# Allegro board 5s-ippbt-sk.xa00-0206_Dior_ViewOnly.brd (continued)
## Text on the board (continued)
BOTTOM: list("[Physical] BOTTOM" "89.Pad/Pad Direct Connect" "NOT_ALLOWED [(PWR_20)]" "ALL_ALLOWED" "" "DRC ERROR CLASS/BOTTOM" "[ThruPin] GND (<uTiL>cId2142<uTiL>.29) (-71.0 1946.0)" "[SmdPin] GND (<uTiL>cId2142<uTiL>.25) (-35.0 1910.0)" list(-71.000000 1946.000000) nil)@@@list("amy_chou" "2015/01/12 09:58:12" nil "P143000034-PC" "5s-ippbt-sk.x01")@@@list("jennifer_hsu" "2015/01/12 14:37:07" nil "p143000039-pc" "5s-ippbt-sk.x01") | list("[Physical] BOTTOM" "91.Pad/Pad Direct Connect" "NOT_ALLOWED [(PWR_20)]" "ALL_ALLOWED" "" "DRC ERROR CLASS/BOTTOM" "[ThruPin] GND (<uTiL>cId2142<uTiL>.28) (-71.0 1874.0)" "[SmdPin] GND (<uTiL>cId2142<uTiL>.25) (-35.0 1910.0)" list(-71.000000 1874.000000) nil)@@@list("amy_chou" "2015/01/12 09:58:14" nil "P143000034-PC" "5s-ippbt-sk.x01")@@@list("jennifer_hsu" "2015/01/12 14:37:08" nil "p143000039-pc" "5s-ippbt-sk.x01") | list("[Physical] BOTTOM" "88.Pad/Pad Direct Connect" "NOT_ALLOWED [(PWR_20)]" "ALL_ALLOWED" "" "DRC ERROR CLASS/BOTTOM" "[ThruPin] GND (<uTiL>cId2142<uTiL>.27) (1.0 1946.0)" "[SmdPin] GND (<uTiL>cId2142<uTiL>.25) (-35.0 1910.0)" list(1.000000 1946.000000) nil)@@@list("amy_chou" "2015/01/12 09:58:12" nil "P143000034-PC" "5s-ippbt-sk.x01")@@@list("jennifer_hsu" "2015/01/12 14:37:07" nil "p143000039-pc" "5s-ippbt-sk.x01") | list("[Physical] BOTTOM" "90.Pad/Pad Direct Connect" "NOT_ALLOWED [(PWR_20)]" "ALL_ALLOWED" "" "DRC ERROR CLASS/BOTTOM" "[ThruPin] GND (<uTiL>cId2142<uTiL>.26) (1.0 1874.0)" "[SmdPin] GND (<uTiL>cId2142<uTiL>.25) (-35.0 1910.0)" list(1.000000 1874.000000) nil)@@@list("amy_chou" "2015/01/12 09:58:13" nil "P143000034-PC" "5s-ippbt-sk.x01")@@@list("jennifer_hsu" "2015/01/12 14:37:08" nil "p143000039-pc" "5s-ippbt-sk.x01") | list("[Physical] BOTTOM" "93.Pad/Pad Direct Connect" "NOT_ALLOWED [(PWR_20)]" "ALL_ALLOWED" "" "DRC ERROR CLASS/BOTTOM" "[ThruPin] GND (<uTiL>cId4668<uTiL>.23) (79.5 2715.5)" "[SmdPin] GND (<uTiL>cId4668<uTiL>.21) (100.0 2695.0)" list(79.500000 2715.500000) nil)@@@list("amy_chou" "2015/01/12 09:58:15" nil "P143000034-PC" "5s-ippbt-sk.x01")@@@list("jennifer_hsu" "2015/01/12 14:37:09" nil "p143000039-pc" "5s-ippbt-sk.x01") | list("[Physical] BOTTOM" "95.Pad/Pad Direct Connect" "NOT_ALLOWED [(PWR_20)]" "ALL_ALLOWED" "" "DRC ERROR CLASS/BOTTOM" "[ThruPin] GND (<uTiL>cId4668<uTiL>.25) (79.5 2674.5)" "[SmdPin] GND (<uTiL>cId4668<uTiL>.21) (100.0 2695.0)" list(79.500000 2674.500000) nil)@@@list("amy_chou" "2015/01/12 09:58:16" nil "P143000034-PC" "5s-ippbt-sk.x01")@@@list("jennifer_hsu" "2015/01/12 14:37:09" nil "p143000039-pc" "5s-ippbt-sk.x01") | list("[Physical] BOTTOM" "99.Pad/Pad Direct Connect" "NOT_ALLOWED [(PWR_20)]" "ALL_ALLOWED" "" "DRC ERROR CLASS/BOTTOM" "[ThruPin] GND (<uTiL>cId3539<uTiL>.22) (109.5 960.5)" "[SmdPin] GND (<uTiL>cId3539<uTiL>.21) (130.0 940.0)" list(109.500000 960.500000) nil)@@@list("amy_chou" "2015/01/12 09:58:18" nil "P143000034-PC" "5s-ippbt-sk.x01")@@@list("jennifer_hsu" "2015/01/12 14:37:11" nil "p143000039-pc" "5s-ippbt-sk.x01") | list("[Physical] BOTTOM" "98.Pad/Pad Direct Connect" "NOT_ALLOWED [(PWR_20)]" "ALL_ALLOWED" "" "DRC ERROR CLASS/BOTTOM" "[ThruPin] GND (<uTiL>cId3539<uTiL>.23) (109.5 919.5)" "[SmdPin] GND (<uTiL>cId3539<uTiL>.21) (130.0 940.0)" list(109.500000 919.500000) nil)@@@list("amy_chou" "2015/01/12 09:58:18" nil "P143000034-PC" "5s-ippbt-sk.x01")@@@list("jennifer_hsu" "2015/01/12 14:37:10" nil "p143000039-pc" "5s-ippbt-sk.x01") | list("[Physical] BOTTOM" "92.Pad/Pad Direct Connect" "NOT_ALLOWED [(PWR_20)]" "ALL_ALLOWED" "" "DRC ERROR CLASS/BOTTOM" "[ThruPin] GND (<uTiL>cId4668<uTiL>.22) (120.5 2715.5)" "[SmdPin] GND (<uTiL>cId4668<uTiL>.21) (100.0 2695.0)" list(120.500000 2715.500000) nil)@@@list("amy_chou" "2015/01/12 09:58:14" nil "P143000034-PC" "5s-ippbt-sk.x01")@@@list("jennifer_hsu" "2015/01/12 14:37:08" nil "p143000039-pc" "5s-ippbt-sk.x01") | list("[Physical] BOTTOM" "94.Pad/Pad Direct Connect" "NOT_ALLOWED [(PWR_20)]" "ALL_ALLOWED" "" "DRC ERROR CLASS/BOTTOM" "[ThruPin] GND (<uTiL>cId4668<uTiL>.24) (120.5 2674.5)" "[SmdPin] GND (<uTiL>cId4668<uTiL>.21) (100.0 2695.0)" list(120.500000 2674.500000) nil)@@@list("amy_chou" "2015/01/12 09:58:15" nil "P143000034-PC" "5s-ippbt-sk.x01")@@@list("jennifer_hsu" "2015/01/12 14:37:09" nil "p143000039-pc" "5s-ippbt-sk.x01") | list("[Physical] BOTTOM" "97.Pad/Pad Direct Connect" "NOT_ALLOWED [(PWR_20)]" "ALL_ALLOWED" "" "DRC ERROR CLASS/BOTTOM" "[ThruPin] GND (<uTiL>cId3539<uTiL>.24) (150.5 960.5)" "[SmdPin] GND (<uTiL>cId3539<uTiL>.21) (130.0 940.0)" list(150.500000 960.500000) nil)@@@list("amy_chou" "2015/01/12 09:58:17" nil "P143000034-PC" "5s-ippbt-sk.x01")@@@list("jennifer_hsu" "2015/01/12 14:37:10" nil "p143000039-pc" "5s-ippbt-sk.x01") | list("[Physical] BOTTOM" "96.Pad/Pad Direct Connect" "NOT_ALLOWED [(PWR_20)]" "ALL_ALLOWED" "" "DRC ERROR CLASS/BOTTOM" "[ThruPin] GND (<uTiL>cId3539<uTiL>.25) (150.5 919.5)" "[SmdPin] GND (<uTiL>cId3539<uTiL>.21) (130.0 940.0)" list(150.500000 919.500000) nil)@@@list("amy_chou" "2015/01/12 09:58:16" nil "P143000034-PC" "5s-ippbt-sk.x01")@@@list("jennifer_hsu" "2015/01/12 14:37:10" nil "p143000039-pc" "5s-ippbt-sk.x01") | list("[Physical] BOTTOM" "83.Pad/Pad Direct Connect" "NOT_ALLOWED [(PWR_20)]" "ALL_ALLOWED" "" "DRC ERROR CLASS/BOTTOM" "[SmdPin] +1P5V (<uTiL>cId4455<uTiL>.2) (930.5 490.0)" "[SmdPin] +1P5V (<uTiL>cId4514<uTiL>.1) (935.0 497.62)" list(935.000000 497.620000) nil)@@@list("amy_chou" "2015/01/12 09:58:09" nil "P143000034-PC" "5s-ippbt-sk.x01")@@@list("jennifer_hsu" "2015/01/12 14:37:05" nil "p143000039-pc" "5s-ippbt-sk.x01") | list("[Physical] BOTTOM" "67.Pad/Pad Direct Connect" "NOT_ALLOWED [100OHM(DP_4/10|9/2.5/200)]" "ALL_ALLOWED" "" "DRC ERROR CLASS/BOTTOM" "[SmdPin] LAN_MDI0_P_C (<uTiL>cId4647<uTiL>.2) (1273.27 3573.46)" "[SmdPin] LAN_MDI0_P_C (<uTiL>cId4415<uTiL>.1) (1274.25 3572.48)" list(1274.250000 3572.480000) nil)@@@list("amy_chou" "2015/01/12 09:58:00" nil "P143000034-PC" "5s-ippbt-sk.x01")@@@list("jennifer_hsu" "2015/01/12 14:36:59" nil "p143000039-pc" "5s-ippbt-sk.x01") | list("[Physical] BOTTOM" "68.Pad/Pad Direct Connect" "NOT_ALLOWED [100OHM(DP_4/10|9/2.5/200)]" "ALL_ALLOWED" "" "DRC ERROR CLASS/BOTTOM" "[SmdPin] LAN_MDI0_P (<uTiL>cId4647<uTiL>.1) (1273.27 3506.54)" "[SmdPin] LAN_MDI0_P (<uTiL>cId4415<uTiL>.2) (1274.25 3507.52)" list(1274.250000 3507.520000) nil)@@@list("amy_chou" "2015/01/12 09:58:00" nil "P143000034-PC" "5s-ippbt-sk.x01")@@@list("jennifer_hsu" "2015/01/12 14:36:59" nil "p143000039-pc" "5s-ippbt-sk.x01") | list("[Physical] BOTTOM" "69.Pad/Pad Direct Connect" "NOT_ALLOWED [100OHM(DP_4/10|9/2.5/200)]" "ALL_ALLOWED" "" "DRC ERROR CLASS/BOTTOM" "[SmdPin] LAN_MDI0_N_C (<uTiL>cId4647<uTiL>.3) (1306.73 3573.46)" "[SmdPin] LAN_MDI0_N_C (<uTiL>cId4415<uTiL>.3) (1305.75 3572.48)" list(1305.750000 3572.480000) nil)@@@list("amy_chou" "2015/01/12 09:58:01" nil "P143000034-PC" "5s-ippbt-sk.x01")@@@list("jennifer_hsu" "2015/01/12 14:36:59" nil "p143000039-pc" "5s-ippbt-sk.x01") | list("[Physical] BOTTOM" "70.Pad/Pad Direct Connect" "NOT_ALLOWED [100OHM(DP_4/10|9/2.5/200)]" "ALL_ALLOWED" "" "DRC ERROR CLASS/BOTTOM" "[SmdPin] LAN_MDI0_N (<uTiL>cId4647<uTiL>.4) (1306.73 3506.54)" "[SmdPin] LAN_MDI0_N (<uTiL>cId4415<uTiL>.4) (1305.75 3507.52)" list(1305.750000 3507.520000) nil)@@@list("amy_chou" "2015/01/12 09:58:01" nil "P143000034-PC" "5s-ippbt-sk.x01")@@@list("jennifer_hsu" "2015/01/12 14:37:00" nil "p143000039-pc" "5s-ippbt-sk.x01") | list("[Physical] BOTTOM" "63.Pad/Pad Direct Connect" "NOT_ALLOWED [100OHM(DP_4/10|9/2.5/200)]" "ALL_ALLOWED" "" "DRC ERROR CLASS/BOTTOM" "[SmdPin] LAN_MDI1_P_C (<uTiL>cId4646<uTiL>.2) (1363.27 3573.46)" "[SmdPin] LAN_MDI1_P_C (<uTiL>cId4414<uTiL>.1) (1364.25 3572.48)" list(1364.250000 3572.480000) nil)@@@list("amy_chou" "2015/01/12 09:57:57" nil "P143000034-PC" "5s-ippbt-sk.x01")@@@list("jennifer_hsu" "2015/01/12 14:36:57" nil "p143000039-pc" "5s-ippbt-sk.x01") | list("[Physical] BOTTOM" "64.Pad/Pad Direct Connect" "NOT_ALLOWED [100OHM(DP_4/10|9/2.5/200)]" "ALL_ALLOWED" "" "DRC ERROR CLASS/BOTTOM" "[SmdPin] LAN_MDI1_P (<uTiL>cId4646<uTiL>.1) (1363.27 3506.54)" "[SmdPin] LAN_MDI1_P (<uTiL>cId4414<uTiL>.2) (1364.25 3507.52)" list(1364.250000 3507.520000) nil)@@@list("amy_chou" "2015/01/12 09:57:58" nil "P143000034-PC" "5s-ippbt-sk.x01")@@@list("jennifer_hsu" "2015/01/12 14:36:57" nil "p143000039-pc" "5s-ippbt-sk.x01") | list("[Physical] BOTTOM" "65.Pad/Pad Direct Connect" "NOT_ALLOWED [100OHM(DP_4/10|9/2.5/200)]" "ALL_ALLOWED" "" "DRC ERROR CLASS/BOTTOM" "[SmdPin] LAN_MDI1_N_C (<uTiL>cId4646<uTiL>.3) (1396.73 3573.46)" "[SmdPin] LAN_MDI1_N_C (<uTiL>cId4414<uTiL>.3) (1395.75 3572.48)" list(1395.750000 3572.480000) nil)@@@list("amy_chou" "2015/01/12 09:57:59" nil "P143000034-PC" "5s-ippbt-sk.x01")@@@list("jennifer_hsu" "2015/01/12 14:36:58" nil "p143000039-pc" "5s-ippbt-sk.x01") | list("[Physical] BOTTOM" "66.Pad/Pad Direct Connect" "NOT_ALLOWED [100OHM(DP_4/10|9/2.5/200)]" "ALL_ALLOWED" "" "DRC ERROR CLASS/BOTTOM" "[SmdPin] LAN_MDI1_N (<uTiL>cId4646<uTiL>.4) (1396.73 3506.54)" "[SmdPin] LAN_MDI1_N (<uTiL>cId4414<uTiL>.4) (1395.75 3507.52)" list(1395.750000 3507.520000) nil)@@@list("amy_chou" "2015/01/12 09:57:59" nil "P143000034-PC" "5s-ippbt-sk.x01")@@@list("jennifer_hsu" "2015/01/12 14:36:58" nil "p143000039-pc" "5s-ippbt-sk.x01") | list("[Physical] BOTTOM" "75.Pad/Pad Direct Connect" "NOT_ALLOWED [100OHM(DP_4/10|9/2.5/200)]" "ALL_ALLOWED" "" "DRC ERROR CLASS/BOTTOM" "[SmdPin] LAN_MDI3_N_C (<uTiL>cId4644<uTiL>.3) (1479.54 3719.73)" "[SmdPin] LAN_MDI3_N_C (<uTiL>cId4412<uTiL>.3) (1480.52 3718.75)" list(1480.520000 3718.750000) nil)@@@list("amy_chou" "2015/01/12 09:58:05" nil "P143000034-PC" "5s-ippbt-sk.x01")@@@list("jennifer_hsu" "2015/01/12 14:37:02" nil "p143000039-pc" "5s-ippbt-sk.x01") | list("[Physical] BOTTOM" "77.Pad/Pad Direct Connect" "NOT_ALLOWED [100OHM(DP_4/10|9/2.5/200)]" "ALL_ALLOWED" "" "DRC ERROR CLASS/BOTTOM" "[SmdPin] LAN_MDI3_P_C (<uTiL>cId4644<uTiL>.2) (1479.54 3686.27)" "[SmdPin] LAN_MDI3_P_C (<uTiL>cId4412<uTiL>.1) (1480.52 3687.25)" list(1480.520000 3687.250000) nil)@@@list("amy_chou" "2015/01/12 09:58:06" nil "P143000034-PC" "5s-ippbt-sk.x01")@@@list("jennifer_hsu" "2015/01/12 14:37:03" nil "p143000039-pc" "5s-ippbt-sk.x01") | list("[Physical] BOTTOM" "73.Pad/Pad Direct Connect" "NOT_ALLOWED [100OHM(DP_4/10|9/2.5/200)]" "ALL_ALLOWED" "" "DRC ERROR CLASS/BOTTOM" "[SmdPin] LAN_MDI2_N_C (<uTiL>cId4645<uTiL>.3) (1481.54 3621.73)" "[SmdPin] LAN_MDI2_N_C (<uTiL>cId4413<uTiL>.3) (1482.52 3620.75)" list(1482.520000 3620.750000) nil)@@@list("amy_chou" "2015/01/12 09:58:03" nil "P143000034-PC" "5s-ippbt-sk.x01")@@@list("jennifer_hsu" "2015/01/12 14:37:01" nil "p143000039-pc" "5s-ippbt-sk.x01") | list("[Physical] BOTTOM" "71.Pad/Pad Direct Connect" "NOT_ALLOWED [100OHM(DP_4/10|9/2.5/200)]" "ALL_ALLOWED" "" "DRC ERROR CLASS/BOTTOM" "[SmdPin] LAN_MDI2_P_C (<uTiL>cId4645<uTiL>.2) (1481.54 3588.27)" "[SmdPin] LAN_MDI2_P_C (<uTiL>cId4413<uTiL>.1) (1482.52 3589.25)" list(1482.520000 3589.250000) nil)@@@list("amy_chou" "2015/01/12 09:58:02" nil "P143000034-PC" "5s-ippbt-sk.x01")@@@list("jennifer_hsu" "2015/01/12 14:37:00" nil "p143000039-pc" "5s-ippbt-sk.x01") | list("[Physical] BOTTOM" "76.Pad/Pad Direct Connect" "NOT_ALLOWED [100OHM(DP_4/10|9/2.5/200)]" "ALL_ALLOWED" "" "DRC ERROR CLASS/BOTTOM" "[SmdPin] LAN_MDI3_N (<uTiL>cId4644<uTiL>.4) (1546.46 3719.73)" "[SmdPin] LAN_MDI3_N (<uTiL>cId4412<uTiL>.4) (1545.48 3718.75)" list(1545.480000 3718.750000) nil)@@@list("amy_chou" "2015/01/12 09:58:05" nil "P143000034-PC" "5s-ippbt-sk.x01")@@@list("jennifer_hsu" "2015/01/12 14:37:02" nil "p143000039-pc" "5s-ippbt-sk.x01") | list("[Physical] BOTTOM" "78.Pad/Pad Direct Connect" "NOT_ALLOWED [100OHM(DP_4/10|9/2.5/200)]" "ALL_ALLOWED" "" "DRC ERROR CLASS/BOTTOM" "[SmdPin] LAN_MDI3_P (<uTiL>cId4644<uTiL>.1) (1546.46 3686.27)" "[SmdPin] LAN_MDI3_P (<uTiL>cId4412<uTiL>.2) (1545.48 3687.25)" list(1545.480000 3687.250000) nil)@@@list("amy_chou" "2015/01/12 09:58:06" nil "P143000034-PC" "5s-ippbt-sk.x01")@@@list("jennifer_hsu" "2015/01/12 14:37:03" nil "p143000039-pc" "5s-ippbt-sk.x01") | list("[Physical] BOTTOM" "74.Pad/Pad Direct Connect" "NOT_ALLOWED [100OHM(DP_4/10|9/2.5/200)]" "ALL_ALLOWED" "" "DRC ERROR CLASS/BOTTOM" "[SmdPin] LAN_MDI2_N (<uTiL>cId4645<uTiL>.4) (1548.46 3621.73)" "[SmdPin] LAN_MDI2_N (<uTiL>cId4413<uTiL>.4) (1547.48 3620.75)" list(1547.480000 3620.750000) nil)@@@list("amy_chou" "2015/01/12 09:58:04" nil "P143000034-PC" "5s-ippbt-sk.x01")@@@list("jennifer_hsu" "2015/01/12 14:37:02" nil "p143000039-pc" "5s-ippbt-sk.x01") | list("[Physical] BOTTOM" "72.Pad/Pad Direct Connect" "NOT_ALLOWED [100OHM(DP_4/10|9/2.5/200)]" "ALL_ALLOWED" "" "DRC ERROR CLASS/BOTTOM" "[SmdPin] LAN_MDI2_P (<uTiL>cId4645<uTiL>.1) (1548.46 3588.27)" "[SmdPin] LAN_MDI2_P (<uTiL>cId4413<uTiL>.2) (1547.48 3589.25)" list(1547.480000 3589.250000) nil)@@@list("amy_chou" "2015/01/12 09:58:02" nil "P143000034-PC" "5s-ippbt-sk.x01")@@@list("jennifer_hsu" "2015/01/12 14:37:01" nil "p143000039-pc" "5s-ippbt-sk.x01") | list("[Physical] BOTTOM" "103.Pad/Pad Direct Connect" "NOT_ALLOWED [(PWR_20)]" "ALL_ALLOWED" "" "DRC ERROR CLASS/BOTTOM" "[ThruPin] GND (<uTiL>cId3651<uTiL>.41) (1649.5 3500.5)" "[SmdPin] GND (<uTiL>cId3651<uTiL>.33) (1690.0 3460.0)" list(1649.500000 3500.500000) nil)@@@list("amy_chou" "2015/01/12 09:58:21" nil "P143000034-PC" "5s-ippbt-sk.x01")@@@list("jennifer_hsu" "2015/01/12 14:37:13" nil "p143000039-pc" "5s-ippbt-sk.x01") | list("[Physical] BOTTOM" "102.Pad/Pad Direct Connect" "NOT_ALLOWED [(PWR_20)]" "ALL_ALLOWED" "" "DRC ERROR CLASS/BOTTOM" "[ThruPin] GND (<uTiL>cId3651<uTiL>.40) (1649.5 3480.5)" "[SmdPin] GND (<uTiL>cId3651<uTiL>.33) (1690.0 3460.0)" list(1649.500000 3480.500000) nil)@@@list("amy_chou" "2015/01/12 09:58:20" nil "P143000034-PC" "5s-ippbt-sk.x01")@@@list("jennifer_hsu" "2015/01/12 14:37:12" nil "p143000039-pc" "5s-ippbt-sk.x01") | list("[Physical] BOTTOM" "107.Pad/Pad Direct Connect" "NOT_ALLOWED [(PWR_20)]" "ALL_ALLOWED" "" "DRC ERROR CLASS/BOTTOM" "[ThruPin] GND (<uTiL>cId3651<uTiL>.39) (1649.5 3439.5)" "[SmdPin] GND (<uTiL>cId3651<uTiL>.33) (1690.0 3460.0)" list(1649.500000 3439.500000) nil)@@@list("amy_chou" "2015/01/12 09:58:24" nil "P143000034-PC" "5s-ippbt-sk.x01")@@@list("jennifer_hsu" "2015/01/12 14:37:14" nil "p143000039-pc" "5s-ippbt-sk.x01") | list("[Physical] BOTTOM" "106.Pad/Pad Direct Connect" "NOT_ALLOWED [(PWR_20)]" "ALL_ALLOWED" "" "DRC ERROR CLASS/BOTTOM" "[ThruPin] GND (<uTiL>cId3651<uTiL>.38) (1649.5 3419.5)" "[SmdPin] GND (<uTiL>cId3651<uTiL>.33) (1690.0 3460.0)" list(1649.500000 3419.500000) nil)@@@list("amy_chou" "2015/01/12 09:58:23" nil "P143000034-PC" "5s-ippbt-sk.x01")@@@list("jennifer_hsu" "2015/01/12 14:37:14" nil "p143000039-pc" "5s-ippbt-sk.x01") | list("[Physical] BOTTOM" "101.Pad/Pad Direct Connect" "NOT_ALLOWED [(PWR_20)]" "ALL_ALLOWED" "" "DRC ERROR CLASS/BOTTOM" "[ThruPin] GND (<uTiL>cId3651<uTiL>.37) (1730.5 3500.5)" "[SmdPin] GND (<uTiL>cId3651<uTiL>.33) (1690.0 3460.0)" list(1730.500000 3500.500000) nil)@@@list("amy_chou" "2015/01/12 09:58:20" nil "P143000034-PC" "5s-ippbt-sk.x01")@@@list("jennifer_hsu" "2015/01/12 14:37:12" nil "p143000039-pc" "5s-ippbt-sk.x01") | list("[Physical] BOTTOM" "100.Pad/Pad Direct Connect" "NOT_ALLOWED [(PWR_20)]" "ALL_ALLOWED" "" "DRC ERROR CLASS/BOTTOM" "[ThruPin] GND (<uTiL>cId3651<uTiL>.36) (1730.5 3480.5)" "[SmdPin] GND (<uTiL>cId3651<uTiL>.33) (1690.0 3460.0)" list(1730.500000 3480.500000) nil)@@@list("amy_chou" "2015/01/12 09:58:19" nil "P143000034-PC" "5s-ippbt-sk.x01")@@@list("jennifer_hsu" "2015/01/12 14:37:11" nil "p143000039-pc" "5s-ippbt-sk.x01") | list("[Physical] BOTTOM" "105.Pad/Pad Direct Connect" "NOT_ALLOWED [(PWR_20)]" "ALL_ALLOWED" "" "DRC ERROR CLASS/BOTTOM" "[ThruPin] GND (<uTiL>cId3651<uTiL>.35) (1730.5 3439.5)" "[SmdPin] GND (<uTiL>cId3651<uTiL>.33) (1690.0 3460.0)" list(1730.500000 3439.500000) nil)@@@list("amy_chou" "2015/01/12 09:58:23" nil "P143000034-PC" "5s-ippbt-sk.x01")@@@list("jennifer_hsu" "2015/01/12 14:37:14" nil "p143000039-pc" "5s-ippbt-sk.x01") | list("[Physical] BOTTOM" "104.Pad/Pad Direct Connect" "NOT_ALLOWED [(PWR_20)]" "ALL_ALLOWED" "" "DRC ERROR CLASS/BOTTOM" "[ThruPin] GND (<uTiL>cId3651<uTiL>.34) (1730.5 3419.5)" "[SmdPin] GND (<uTiL>cId3651<uTiL>.33) (1690.0 3460.0)" list(1730.500000 3419.500000) nil)@@@list("amy_chou" "2015/01/12 09:58:22" nil "P143000034-PC" "5s-ippbt-sk.x01")@@@list("jennifer_hsu" "2015/01/12 14:37:13" nil "p143000039-pc" "5s-ippbt-sk.x01") | list("[Spacing] BOTTOM" "43.SMD Pin to SMD Pin Same Net" "5 MIL [DEFAULT]" "3.51 MIL" "1.49 MIL" "DRC ERROR CLASS/BOTTOM" "[SmdPin] GND (<uTiL>cId3537<uTiL>.BH53) (1908.88 1499.72)" "[SmdPin] GND (<uTiL>cId3537<uTiL>.BJ52) (1925.86 1482.74)" list(1916.130000 1492.470000) nil)@@@list("amy_chou" "2015/01/12 09:57:46" nil "P143000034-PC" "5s-ippbt-sk.x01")@@@list("jennifer_hsu" "2015/01/12 14:36:50" nil "p143000039-pc" "5s-ippbt-sk.x01") | list("[Spacing] BOTTOM" "46.SMD Pin to SMD Pin Same Net" "5 MIL [[B]=4]" "3.51 MIL" "1.49 MIL" "DRC ERROR CLASS/BOTTOM" "[SmdPin] GND (<uTiL>cId3537<uTiL>.A52) (1925.86 2412.98)" "[SmdPin] GND (<uTiL>cId3537<uTiL>.B53) (1908.88 2396.0)" list(1918.610000 2405.730000) nil)@@@list("amy_chou" "2015/01/12 09:57:48" nil "P143000034-PC" "5s-ippbt-sk.x01")@@@list("jennifer_hsu" "2015/01/12 14:36:51" nil "p143000039-pc" "5s-ippbt-sk.x01") | list("[Physical] BOTTOM" "109.Pad/Pad Direct Connect" "NOT_ALLOWED [(PWR_20)]" "ALL_ALLOWED" "" "DRC ERROR CLASS/BOTTOM" "[ThruPin] GND (<uTiL>cId4828<uTiL>.32) (2121.0 3169.0)" "[SmdPin] GND (<uTiL>cId4828<uTiL>.29) (2180.0 3110.0)" list(2121.000000 3169.000000) nil)@@@list("amy_chou" "2015/01/12 09:58:25" nil "P143000034-PC" "5s-ippbt-sk.x01")@@@list("jennifer_hsu" "2015/01/12 14:37:15" nil "p143000039-pc" "5s-ippbt-sk.x01") | list("[Physical] BOTTOM" "111.Pad/Pad Direct Connect" "NOT_ALLOWED [(PWR_20)]" "ALL_ALLOWED" "" "DRC ERROR CLASS/BOTTOM" "[ThruPin] GND (<uTiL>cId4828<uTiL>.30) (2121.0 3051.0)" "[SmdPin] GND (<uTiL>cId4828<uTiL>.29) (2180.0 3110.0)" list(2121.000000 3051.000000) nil)@@@list("amy_chou" "2015/01/12 09:58:26" nil "P143000034-PC" "5s-ippbt-sk.x01")@@@list("jennifer_hsu" "2015/01/12 14:37:16" nil "p143000039-pc" "5s-ippbt-sk.x01") | list("[Physical] BOTTOM" "108.Pad/Pad Direct Connect" "NOT_ALLOWED [(PWR_20)]" "ALL_ALLOWED" "" "DRC ERROR CLASS/BOTTOM" "[ThruPin] GND (<uTiL>cId4828<uTiL>.33) (2239.0 3169.0)" "[SmdPin] GND (<uTiL>cId4828<uTiL>.29) (2180.0 3110.0)" list(2239.000000 3169.000000) nil)@@@list("amy_chou" "2015/01/12 09:58:24" nil "P143000034-PC" "5s-ippbt-sk.x01")@@@list("jennifer_hsu" "2015/01/12 14:37:15" nil "p143000039-pc" "5s-ippbt-sk.x01") | list("[Physical] BOTTOM" "110.Pad/Pad Direct Connect" "NOT_ALLOWED [(PWR_20)]" "ALL_ALLOWED" "" "DRC ERROR CLASS/BOTTOM" "[ThruPin] GND (<uTiL>cId4828<uTiL>.31) (2239.0 3051.0)" "[SmdPin] GND (<uTiL>cId4828<uTiL>.29) (2180.0 3110.0)" list(2239.000000 3051.000000) nil)@@@list("amy_chou" "2015/01/12 09:58:25" nil "P143000034-PC" "5s-ippbt-sk.x01")@@@list("jennifer_hsu" "2015/01/12 14:37:15" nil "p143000039-pc" "5s-ippbt-sk.x01") | list("[Physical] BOTTOM" "79.Pad/Pad Direct Connect" "NOT_ALLOWED [DEFAULT]" "ALL_ALLOWED" "" "DRC ERROR CLASS/BOTTOM" "[SmdPin] EC_AGND (<uTiL>cId2650<uTiL>.2) (2375.0 784.5)" "[SmdPin] EC_AGND (<uTiL>cId2478<uTiL>.2) (2374.0 765.0)" list(2375.000000 784.500000) nil)@@@list("amy_chou" "2015/01/12 09:58:07" nil "P143000034-PC" "5s-ippbt-sk.x01")@@@list("jennifer_hsu" "2015/01/12 14:37:04" nil "p143000039-pc" "5s-ippbt-sk.x01") | list("[Spacing] BOTTOM" "47.SMD Pin to SMD Pin Same Net" "5 MIL [[B]=4]" "3.51 MIL" "1.49 MIL" "DRC ERROR CLASS/BOTTOM" "[SmdPin] GND (<uTiL>cId3537<uTiL>.A3) (2883.9 2412.98)" "[SmdPin] GND (<uTiL>cId3537<uTiL>.B2) (2900.88 2396.0)" list(2891.150000 2405.730000) nil)@@@list("amy_chou" "2015/01/12 09:57:48" nil "P143000034-PC" "5s-ippbt-sk.x01")@@@list("jennifer_hsu" "2015/01/12 14:36:51" nil "p143000039-pc" "5s-ippbt-sk.x01") | list("[Spacing] BOTTOM" "45.SMD Pin to SMD Pin Same Net" "5 MIL [[B]=4]" "3.51 MIL" "1.49 MIL" "DRC ERROR CLASS/BOTTOM" "[SmdPin] GND (<uTiL>cId3537<uTiL>.B2) (2900.88 2396.0)" "[SmdPin] GND (<uTiL>cId3537<uTiL>.C1) (2917.86 2379.02)" list(2908.130000 2388.750000) nil)@@@list("amy_chou" "2015/01/12 09:57:47" nil "P143000034-PC" "5s-ippbt-sk.x01")@@@list("jennifer_hsu" "2015/01/12 14:36:51" nil "p143000039-pc" "5s-ippbt-sk.x01") | list("[Spacing] BOTTOM" "44.SMD Pin to SMD Pin Same Net" "5 MIL [DEFAULT]" "3.51 MIL" "1.49 MIL" "DRC ERROR CLASS/BOTTOM" "[SmdPin] GND (<uTiL>cId3537<uTiL>.BH1) (2917.86 1499.72)" "[SmdPin] GND (<uTiL>cId3537<uTiL>.BJ2) (2900.88 1482.74)" list(2910.610000 1492.470000) nil)@@@list("amy_chou" "2015/01/12 09:57:47" nil "P143000034-PC" "5s-ippbt-sk.x01")@@@list("jennifer_hsu" "2015/01/12 14:36:50" nil "p143000039-pc" "5s-ippbt-sk.x01") | list("[Spacing] BOTTOM" "40.Drill Hole to Pin" "8 MIL [DEFAULT]" "7.39 MIL" "0.61 MIL" "DRC ERROR CLASS/BOTTOM" "[ThruPin] Dummy (<uTiL>cId2813<uTiL>.3) (3063.0 -5.87)" "[ThruPin] Q32_C (<uTiL>cId2813<uTiL>.L2) (3110.24 2.0)" list(3082.730000 -2.580000) nil)@@@list("amy_chou" "2015/01/12 09:57:44" nil "P143000034-PC" "5s-ippbt-sk.x01")@@@list("jennifer_hsu" "2015/01/12 14:36:49" nil "p143000039-pc" "5s-ippbt-sk.x01") | list("[Spacing] BOTTOM" "39.Drill Hole to Pin" "8 MIL [DEFAULT]" "7.39 MIL" "0.61 MIL" "DRC ERROR CLASS/BOTTOM" "[ThruPin] Dummy (<uTiL>cId2813<uTiL>.4) (3157.48 -5.87)" "[ThruPin] Q32_C (<uTiL>cId2813<uTiL>.L2) (3110.24 2.0)" list(3137.750000 -2.580000) nil)@@@list("amy_chou" "2015/01/12 09:57:44" nil "P143000034-PC" "5s-ippbt-sk.x01")@@@list("jennifer_hsu" "2015/01/12 14:36:49" nil "p143000039-pc" "5s-ippbt-sk.x01") | list("[Physical] BOTTOM" "82.Pad/Pad Direct Connect" "NOT_ALLOWED [(PWR_20)]" "ALL_ALLOWED" "" "DRC ERROR CLASS/BOTTOM" "[SmdPin] +VCORE_PHASE (<uTiL>cId2471<uTiL>.1) (3405.0 3060.5)" "[SmdPin] +VCORE_PHASE (<uTiL>cId2459<uTiL>.1) (3405.0 3104.09)" list(3405.000000 3060.500000) nil)@@@list("amy_chou" "2015/01/12 09:58:08" nil "P143000034-PC" "5s-ippbt-sk.x01")@@@list("jennifer_hsu" "2015/01/12 14:37:05" nil "p143000039-pc" "5s-ippbt-sk.x01") | list("[Physical] BOTTOM" "112.Pad/Pad Direct Connect" "NOT_ALLOWED [(PWR_20)]" "ALL_ALLOWED" "" "DRC ERROR CLASS/BOTTOM" "[SmdPin] +VCORE (<uTiL>cId2459<uTiL>.2) (3405.0 2865.91)" "[SmdPin] +VCORE (<uTiL>cId2470<uTiL>.1) (3405.0 2909.5)" list(3405.000000 2909.500000) nil)@@@list("amy_chou" "2015/01/12 09:58:27" nil "P143000034-PC" "5s-ippbt-sk.x01")@@@list("jennifer_hsu" "2015/01/12 14:37:16" nil "p143000039-pc" "5s-ippbt-sk.x01") | list("[Physical] BOTTOM" "80.Pad/Pad Direct Connect" "NOT_ALLOWED [(PWR_20)]" "ALL_ALLOWED" "" "DRC ERROR CLASS/BOTTOM" "[SmdPin] +VNN (<uTiL>cId2474<uTiL>.1) (3450.0 860.5)" "[SmdPin] +VNN (<uTiL>cId3522<uTiL>.2) (3450.0 904.09)" list(3450.000000 860.500000) nil)@@@list("amy_chou" "2015/01/12 09:58:07" nil "P143000034-PC" "5s-ippbt-sk.x01")@@@list("jennifer_hsu" "2015/01/12 14:37:04" nil "p143000039-pc" "5s-ippbt-sk.x01") | list("[Physical] BOTTOM" "81.Pad/Pad Direct Connect" "NOT_ALLOWED [(PWR_20)]" "ALL_ALLOWED" "" "DRC ERROR CLASS/BOTTOM" "[SmdPin] +V_AXG_PHASE (<uTiL>cId3522<uTiL>.1) (3450.0 665.91)" "[SmdPin] +V_AXG_PHASE (<uTiL>cId2646<uTiL>.1) (3450.0 709.5)" list(3450.000000 709.500000) nil)@@@list("amy_chou" "2015/01/12 09:58:08" nil "P143000034-PC" "5s-ippbt-sk.x01")@@@list("jennifer_hsu" "2015/01/12 14:37:04" nil "p143000039-pc" "5s-ippbt-sk.x01") | list("[Physical] BOTTOM" "87.Pad/Pad Direct Connect" "NOT_ALLOWED [(PWR_20)]" "ALL_ALLOWED" "" "DRC ERROR CLASS/BOTTOM" "[SmdPin] GND (<uTiL>cId4577<uTiL>.33) (3575.0 2020.0)" "[ThruPin] GND (<uTiL>cId4577<uTiL>.37) (3534.5 2060.5)" list(3534.500000 2060.500000) nil)@@@list("amy_chou" "2015/01/12 09:58:11" nil "P143000034-PC" "5s-ippbt-sk.x01")@@@list("jennifer_hsu" "2015/01/12 14:37:06" nil "p143000039-pc" "5s-ippbt-sk.x01") | list("[Physical] BOTTOM" "86.Pad/Pad Direct Connect" "NOT_ALLOWED [(PWR_20)]" "ALL_ALLOWED" "" "DRC ERROR CLASS/BOTTOM" "[SmdPin] GND (<uTiL>cId4577<uTiL>.33) (3575.0 2020.0)" "[ThruPin] GND (<uTiL>cId4577<uTiL>.36) (3534.5 1979.5)" list(3534.500000 1979.500000) nil)@@@list("amy_chou" "2015/01/12 09:58:11" nil "P143000034-PC" "5s-ippbt-sk.x01")@@@list("jennifer_hsu" "2015/01/12 14:37:06" nil "p143000039-pc" "5s-ippbt-sk.x01") | list("[Spacing] BOTTOM" "41.Drill Hole to Pin" "8 MIL [DEFAULT]" "7.39 MIL" "0.61 MIL" "DRC ERROR CLASS/BOTTOM" "[ThruPin] Dummy (<uTiL>cId4667<uTiL>.3) (3572.76 -45.0)" "[ThruPin] PWR_LED- (<uTiL>cId4667<uTiL>.L2) (3620.0 -37.13)" list(3592.490000 -41.710000) nil)@@@list("amy_chou" "2015/01/12 09:57:45" nil "P143000034-PC" "5s-ippbt-sk.x01")@@@list("jennifer_hsu" "2015/01/12 14:36:49" nil "p143000039-pc" "5s-ippbt-sk.x01") | list("[Physical] BOTTOM" "85.Pad/Pad Direct Connect" "NOT_ALLOWED [(PWR_20)]" "ALL_ALLOWED" "" "DRC ERROR CLASS/BOTTOM" "[SmdPin] GND (<uTiL>cId4577<uTiL>.33) (3575.0 2020.0)" "[ThruPin] GND (<uTiL>cId4577<uTiL>.35) (3615.5 2060.5)" list(3615.500000 2060.500000) nil)@@@list("amy_chou" "2015/01/12 09:58:10" nil "P143000034-PC" "5s-ippbt-sk.x01")@@@list("jennifer_hsu" "2015/01/12 14:37:06" nil "p143000039-pc" "5s-ippbt-sk.x01") | list("[Physical] BOTTOM" "84.Pad/Pad Direct Connect" "NOT_ALLOWED [(PWR_20)]" "ALL_ALLOWED" "" "DRC ERROR CLASS/BOTTOM" "[ThruPin] GND (<uTiL>cId4577<uTiL>.34) (3615.5 1979.5)" "[SmdPin] GND (<uTiL>cId4577<uTiL>.33) (3575.0 2020.0)" list(3615.500000 1979.500000) nil)@@@list("amy_chou" "2015/01/12 09:58:09" nil "P143000034-PC" "5s-ippbt-sk.x01")@@@list("jennifer_hsu" "2015/01/12 14:37:05" nil "p143000039-pc" "5s-ippbt-sk.x01") | list("[Spacing] BOTTOM" "42.Drill Hole to Pin" "8 MIL [DEFAULT]" "7.39 MIL" "0.61 MIL" "DRC ERROR CLASS/BOTTOM" "[ThruPin] Dummy (<uTiL>cId4667<uTiL>.4) (3667.24 -45.0)" "[ThruPin] PWR_LED- (<uTiL>cId4667<uTiL>.L2) (3620.0 -37.13)" list(3647.510000 -41.710000) nil)@@@list("amy_chou" "2015/01/12 09:57:46" nil "P143000034-PC" "5s-ippbt-sk.x01")@@@list("jennifer_hsu" "2015/01/12 14:36:50" nil "p143000039-pc" "5s-ippbt-sk.x01") | list("[Spacing] BOTTOM" "41.Shape to Route Keepout" "0 MIL [DEFAULT]" "0 MIL" "0.00 MIL" "DRC ERROR CLASS/BOTTOM" "[Shape] Route Keepout/Bottom ((3896.68 3955.74) (4331.66 4390.72))" "[Bottom Shape] GND ((-373.69 -332.34) (4468.16 4450.45))" list(4114.170000 4390.720000) nil)@@@list("amy_chou" "2015/01/09 17:03:05" nil "P143000034-PC" "5s-ippbt-sk.x01")@@@nil
Ref Des/Silkscreen Bottom: H7 | H23 | H22 | XU1 | J134 | H20 | H21 | H8 | P70 | PU8 | PU3 | Y10 | LU1 | UU3 | Y24 | Y5 | U24 | PU9 | U23 | XMM1 | DDR3L Only
TOP: list("[Physical] TOP" "58.Pad/Pad Direct Connect" "NOT_ALLOWED [(PWR_20)]" "ALL_ALLOWED" "" "DRC ERROR CLASS/TOP" "[ThruPin] GND (<uTiL>cId4340<uTiL>.50) (-9.49 3674.49)" "[SmdPin] GND (<uTiL>cId4340<uTiL>.49) (70.0 3595.0)" list(-9.490000 3674.490000) nil)@@@list("amy_chou" "2015/01/12 09:57:54" nil "P143000034-PC" "5s-ippbt-sk.x01")@@@list("jennifer_hsu" "2015/01/12 14:36:55" nil "p143000039-pc" "5s-ippbt-sk.x01") | list("[Physical] TOP" "62.Pad/Pad Direct Connect" "NOT_ALLOWED [(PWR_20)]" "ALL_ALLOWED" "" "DRC ERROR CLASS/TOP" "[ThruPin] GND (<uTiL>cId4340<uTiL>.54) (-9.49 3515.51)" "[SmdPin] GND (<uTiL>cId4340<uTiL>.49) (70.0 3595.0)" list(-9.490000 3515.510000) nil)@@@list("amy_chou" "2015/01/12 09:57:57" nil "P143000034-PC" "5s-ippbt-sk.x01")@@@list("jennifer_hsu" "2015/01/12 14:36:57" nil "p143000039-pc" "5s-ippbt-sk.x01") | list("[Physical] TOP" "57.Pad/Pad Direct Connect" "NOT_ALLOWED [(PWR_20)]" "ALL_ALLOWED" "" "DRC ERROR CLASS/TOP" "[ThruPin] GND (<uTiL>cId4340<uTiL>.51) (10.51 3674.49)" "[SmdPin] GND (<uTiL>cId4340<uTiL>.49) (70.0 3595.0)" list(10.510000 3674.490000) nil)@@@list("amy_chou" "2015/01/12 09:57:54" nil "P143000034-PC" "5s-ippbt-sk.x01")@@@list("jennifer_hsu" "2015/01/12 14:36:55" nil "p143000039-pc" "5s-ippbt-sk.x01") | list("[Physical] TOP" "61.Pad/Pad Direct Connect" "NOT_ALLOWED [(PWR_20)]" "ALL_ALLOWED" "" "DRC ERROR CLASS/TOP" "[ThruPin] GND (<uTiL>cId4340<uTiL>.55) (10.51 3515.51)" "[SmdPin] GND (<uTiL>cId4340<uTiL>.49) (70.0 3595.0)" list(10.510000 3515.510000) nil)@@@list("amy_chou" "2015/01/12 09:57:56" nil "P143000034-PC" "5s-ippbt-sk.x01")@@@list("jennifer_hsu" "2015/01/12 14:36:56" nil "p143000039-pc" "5s-ippbt-sk.x01") | list("[Physical] TOP" "56.Pad/Pad Direct Connect" "NOT_ALLOWED [(PWR_20)]" "ALL_ALLOWED" "" "DRC ERROR CLASS/TOP" "[ThruPin] GND (<uTiL>cId4340<uTiL>.52) (129.49 3674.49)" "[SmdPin] GND (<uTiL>cId4340<uTiL>.49) (70.0 3595.0)" list(129.490000 3674.490000) nil)@@@list("amy_chou" "2015/01/12 09:57:53" nil "P143000034-PC" "5s-ippbt-sk.x01")@@@list("jennifer_hsu" "2015/01/12 14:36:55" nil "p143000039-pc" "5s-ippbt-sk.x01") | list("[Physical] TOP" "60.Pad/Pad Direct Connect" "NOT_ALLOWED [(PWR_20)]" "ALL_ALLOWED" "" "DRC ERROR CLASS/TOP" "[ThruPin] GND (<uTiL>cId4340<uTiL>.56) (129.49 3515.51)" "[SmdPin] GND (<uTiL>cId4340<uTiL>.49) (70.0 3595.0)" list(129.490000 3515.510000) nil)@@@list("amy_chou" "2015/01/12 09:57:55" nil "P143000034-PC" "5s-ippbt-sk.x01")@@@list("jennifer_hsu" "2015/01/12 14:36:56" nil "p143000039-pc" "5s-ippbt-sk.x01") | list("[Physical] TOP" "55.Pad/Pad Direct Connect" "NOT_ALLOWED [(PWR_20)]" "ALL_ALLOWED" "" "DRC ERROR CLASS/TOP" "[ThruPin] GND (<uTiL>cId4340<uTiL>.53) (149.49 3674.49)" "[SmdPin] GND (<uTiL>cId4340<uTiL>.49) (70.0 3595.0)" list(149.490000 3674.490000) nil)@@@list("amy_chou" "2015/01/12 09:57:53" nil "P143000034-PC" "5s-ippbt-sk.x01")@@@list("jennifer_hsu" "2015/01/12 14:36:54" nil "p143000039-pc" "5s-ippbt-sk.x01") | list("[Physical] TOP" "59.Pad/Pad Direct Connect" "NOT_ALLOWED [(PWR_20)]" "ALL_ALLOWED" "" "DRC ERROR CLASS/TOP" "[ThruPin] GND (<uTiL>cId4340<uTiL>.57) (149.49 3515.51)" "[SmdPin] GND (<uTiL>cId4340<uTiL>.49) (70.0 3595.0)" list(149.490000 3515.510000) nil)@@@list("amy_chou" "2015/01/12 09:57:55" nil "P143000034-PC" "5s-ippbt-sk.x01")@@@list("jennifer_hsu" "2015/01/12 14:36:56" nil "p143000039-pc" "5s-ippbt-sk.x01") | list("[Physical] TOP" "50.Pad/Pad Direct Connect" "NOT_ALLOWED [(PWR_20)]" "ALL_ALLOWED" "" "DRC ERROR CLASS/TOP" "[SmdPin] +1P35V_DUAL (<uTiL>cId4677<uTiL>.1) (546.0 2770.0)" "[SmdPin] +1P35V_DUAL (<uTiL>cId3616<uTiL>.1) (584.04 2774.5)" list(546.000000 2770.000000) nil)@@@list("amy_chou" "2015/01/12 09:57:50" nil "P143000034-PC" "5s-ippbt-sk.x01")@@@list("jennifer_hsu" "2015/01/12 14:36:52" nil "p143000039-pc" "5s-ippbt-sk.x01") | list("[Physical] TOP" "51.Pad/Pad Direct Connect" "NOT_ALLOWED [(PWR_20)]" "ALL_ALLOWED" "" "DRC ERROR CLASS/TOP" "[SmdPin] +5VSB (<uTiL>cId501<uTiL>.1) (828.75 1190.5)" "[SmdPin] +5VSB (<uTiL>cId510<uTiL>.1) (828.75 1245.48)" list(828.750000 1190.500000) nil)@@@list("amy_chou" "2015/01/12 09:57:50" nil "P143000034-PC" "5s-ippbt-sk.x01")@@@list("jennifer_hsu" "2015/01/12 14:36:53" nil "p143000039-pc" "5s-ippbt-sk.x01") | list("[Physical] TOP" "49.Pad/Pad Direct Connect" "NOT_ALLOWED [(PWR_20)]" "ALL_ALLOWED" "" "DRC ERROR CLASS/TOP" "[SmdPin] +1P0V (<uTiL>cId4469<uTiL>.1) (1862.11 1005.0)" "[SmdPin] +1P0V (<uTiL>cId4454<uTiL>.2) (1850.0 1000.5)" list(1850.000000 1000.500000) nil)@@@list("amy_chou" "2015/01/12 09:57:49" nil "P143000034-PC" "5s-ippbt-sk.x01")@@@list("jennifer_hsu" "2015/01/12 14:36:52" nil "p143000039-pc" "5s-ippbt-sk.x01") | list("[Spacing] TOP" "2.Drill Hole to Pin" "8 MIL [DEFAULT]" "7.39 MIL" "0.61 MIL" "DRC ERROR CLASS/TOP" "[ThruPin] Dummy (<uTiL>cId2813<uTiL>.3) (3063.0 -5.87)" "[ThruPin] Q32_C (<uTiL>cId2813<uTiL>.L2) (3110.24 2.0)" list(3082.730000 -2.580000) nil)@@@list("amy_chou" "2015/01/12 09:57:22" nil "P143000034-PC" "5s-ippbt-sk.x01")@@@list("jennifer_hsu" "2015/01/12 14:36:36" nil "p143000039-pc" "5s-ippbt-sk.x01") | list("[Spacing] TOP" "1.Drill Hole to Pin" "8 MIL [DEFAULT]" "7.39 MIL" "0.61 MIL" "DRC ERROR CLASS/TOP" "[ThruPin] Dummy (<uTiL>cId2813<uTiL>.4) (3157.48 -5.87)" "[ThruPin] Q32_C (<uTiL>cId2813<uTiL>.L2) (3110.24 2.0)" list(3137.750000 -2.580000) nil)@@@list("amy_chou" "2015/01/12 09:57:23" nil "P143000034-PC" "5s-ippbt-sk.x01")@@@list("jennifer_hsu" "2015/01/12 14:36:35" nil "p143000039-pc" "5s-ippbt-sk.x01") | list("[Physical] TOP" "53.Pad/Pad Direct Connect" "NOT_ALLOWED [(PWR_20)]" "ALL_ALLOWED" "" "DRC ERROR CLASS/TOP" "[ThruPin] GND (<uTiL>cId165<uTiL>.13) (3405.63 3705.0)" "[SmdPin] GND (<uTiL>cId165<uTiL>.11) (3445.0 3705.0)" list(3405.630000 3705.000000) nil)@@@list("amy_chou" "2015/01/12 09:57:52" nil "P143000034-PC" "5s-ippbt-sk.x01")@@@list("jennifer_hsu" "2015/01/12 14:36:53" nil "p143000039-pc" "5s-ippbt-sk.x01") | list("[Physical] TOP" "54.Pad/Pad Direct Connect" "NOT_ALLOWED [(PWR_20)]" "ALL_ALLOWED" "" "DRC ERROR CLASS/TOP" "[SmdPin] GND (<uTiL>cId165<uTiL>.11) (3445.0 3705.0)" "[ThruPin] GND (<uTiL>cId165<uTiL>.12) (3484.37 3705.0)" list(3484.370000 3705.000000) nil)@@@list("amy_chou" "2015/01/12 09:57:52" nil "P143000034-PC" "5s-ippbt-sk.x01")@@@list("jennifer_hsu" "2015/01/12 14:36:54" nil "p143000039-pc" "5s-ippbt-sk.x01") | list("[Spacing] TOP" "3.Drill Hole to Pin" "8 MIL [DEFAULT]" "7.39 MIL" "0.61 MIL" "DRC ERROR CLASS/TOP" "[ThruPin] Dummy (<uTiL>cId4667<uTiL>.3) (3572.76 -45.0)" "[ThruPin] PWR_LED- (<uTiL>cId4667<uTiL>.L2) (3620.0 -37.13)" list(3592.490000 -41.710000) nil)@@@list("amy_chou" "2015/01/12 09:57:24" nil "P143000034-PC" "5s-ippbt-sk.x01")@@@list("jennifer_hsu" "2015/01/12 14:36:36" nil "p143000039-pc" "5s-ippbt-sk.x01") | list("[Spacing] TOP" "4.Drill Hole to Pin" "8 MIL [DEFAULT]" "7.39 MIL" "0.61 MIL" "DRC ERROR CLASS/TOP" "[ThruPin] Dummy (<uTiL>cId4667<uTiL>.4) (3667.24 -45.0)" "[ThruPin] PWR_LED- (<uTiL>cId4667<uTiL>.L2) (3620.0 -37.13)" list(3647.510000 -41.710000) nil)@@@list("amy_chou" "2015/01/12 09:57:24" nil "P143000034-PC" "5s-ippbt-sk.x01")@@@list("jennifer_hsu" "2015/01/12 14:36:36" nil "p143000039-pc" "5s-ippbt-sk.x01") | list("[Physical] TOP" "48.Pad/Pad Direct Connect" "NOT_ALLOWED [(PWR_20)]" "ALL_ALLOWED" "" "DRC ERROR CLASS/TOP" "[SmdPin] +19VA_IN (<uTiL>cId504<uTiL>.1) (3730.5 3765.0)" "[SmdPin] +19VA_IN (<uTiL>cId4669<uTiL>.1) (3790.0 3764.37)" list(3730.500000 3765.000000) nil)@@@list("amy_chou" "2015/01/12 09:57:49" nil "P143000034-PC" "5s-ippbt-sk.x01")@@@list("jennifer_hsu" "2015/01/12 14:36:52" nil "p143000039-pc" "5s-ippbt-sk.x01") | list("[Physical] TOP" "52.Pad/Pad Direct Connect" "NOT_ALLOWED [(PWR_20)]" "ALL_ALLOWED" "" "DRC ERROR CLASS/TOP" "[SmdPin] +19VA (<uTiL>cId2647<uTiL>.1) (3730.5 3685.0)" "[SmdPin] +19VA (<uTiL>cId4669<uTiL>.2) (3790.0 3685.63)" list(3730.500000 3685.000000) nil)@@@list("amy_chou" "2015/01/12 09:57:51" nil "P143000034-PC" "5s-ippbt-sk.x01")@@@list("jennifer_hsu" "2015/01/12 14:36:53" nil "p143000039-pc" "5s-ippbt-sk.x01")
Ref Des/Silkscreen Top: H14 | AU1 | Long SSD | Short SSD | CR6 | Y12 | SW10 | P13 | XBT1 | 2-4 | Clear CMOS | 1-3 | Clear PW | 3-4 | Default | P110 | E69 | P12 | H1 | H3 | REV:A00 | PCB MADE IN CHINA | H4 | H2 | J56 | J27 | J8 | SFIS | J17 | J137 | J125 | ALL RIGHTS RESERVED | www.dell.com | COPYRIGHT 2015.02 | E4 | PJ1 | J218 | J11 | J133 | J219
VCC: list("[Spacing] VCC" "14.Shape to Route Keepout" "0 MIL [DEFAULT]" "0 MIL" "0.00 MIL" "DRC ERROR CLASS/VCC" "[Shape] Route Keepout/All ((115.69 2506.43) (186.31 2577.05))" "[Vcc Shape] GND ((-373.71 -332.37) (4468.18 4481.96))" list(186.310000 2541.740000) nil)@@@list("amy_chou" "2015/01/12 09:57:29" nil "P143000034-PC" "5s-ippbt-sk.x01")@@@list("jennifer_hsu" "2015/01/12 14:36:40" nil "p143000039-pc" "5s-ippbt-sk.x01") | list("[Spacing] VCC" "5.Shape to Route Keepout" "0 MIL [DEFAULT]" "0 MIL" "0.00 MIL" "DRC ERROR CLASS/VCC" "[Shape] Route Keepout/All ((353.45 4291.46) (424.07 4362.08))" "[Vcc Shape] AGND ((-255.0 3453.0) (720.0 4400.0))" list(424.070000 4326.770000) nil)@@@list("amy_chou" "2015/01/12 09:57:25" nil "P143000034-PC" "5s-ippbt-sk.x01")@@@list("jennifer_hsu" "2015/01/12 14:36:37" nil "p143000039-pc" "5s-ippbt-sk.x01") | list("[Spacing] VCC" "6.Shape to Route Keepout" "0 MIL [DEFAULT]" "0 MIL" "0.00 MIL" "DRC ERROR CLASS/VCC" "[Shape] Route Keepout/All ((609.35 4291.46) (679.98 4362.08))" "[Vcc Shape] AGND ((-255.0 3453.0) (720.0 4400.0))" list(679.980000 4326.770000) nil)@@@list("amy_chou" "2015/01/12 09:57:25" nil "P143000034-PC" "5s-ippbt-sk.x01")@@@list("jennifer_hsu" "2015/01/12 14:36:37" nil "p143000039-pc" "5s-ippbt-sk.x01") | list("[Spacing] VCC" "11.Shape to Route Keepout" "0 MIL [DEFAULT]" "0 MIL" "0.00 MIL" "DRC ERROR CLASS/VCC" "[Shape] Route Keepout/All ((976.14 737.49) (1042.76 804.11))" "[Vcc Shape] GND ((-373.71 -332.37) (4468.18 4481.96))" list(1042.760000 770.800000) nil)@@@list("amy_chou" "2015/01/12 09:57:28" nil "P143000034-PC" "5s-ippbt-sk.x01")@@@list("jennifer_hsu" "2015/01/12 14:36:39" nil "p143000039-pc" "5s-ippbt-sk.x01") | list("[Spacing] VCC" "7.Shape to Route Keepout" "0 MIL [DEFAULT]" "0 MIL" "0.00 MIL" "DRC ERROR CLASS/VCC" "[Shape] Route Keepout/All ((1437.45 -325.97) (1524.07 -239.35))" "[Vcc Shape] GND ((-373.71 -332.37) (4468.18 4481.96))" list(1437.450000 -282.660000) nil)@@@list("amy_chou" "2015/01/12 09:57:26" nil "P143000034-PC" "5s-ippbt-sk.x01")@@@list("jennifer_hsu" "2015/01/12 14:36:37" nil "p143000039-pc" "5s-ippbt-sk.x01") | list("[Spacing] VCC" "15.Shape to Route Keepout" "0 MIL [DEFAULT]" "0 MIL" "0.00 MIL" "DRC ERROR CLASS/VCC" "[Shape] Route Keepout/All ((2391.48 4180.65) (2484.12 4273.28))" "[Vcc Shape] GND ((-373.71 -332.37) (4468.18 4481.96))" list(2484.120000 4226.970000) nil)@@@list("amy_chou" "2015/01/12 09:57:30" nil "P143000034-PC" "5s-ippbt-sk.x01")@@@list("jennifer_hsu" "2015/01/12 14:36:40" nil "p143000039-pc" "5s-ippbt-sk.x01") | list("[Spacing] VCC" "16.Shape to Route Keepout" "0 MIL [DEFAULT]" "0 MIL" "0.00 MIL" "DRC ERROR CLASS/VCC" "[Shape] Route Keepout/All ((2955.52 4114.02) (3036.14 4194.64))" "[Vcc Shape] GND ((-373.71 -332.37) (4468.18 4481.96))" list(3036.140000 4154.330000) nil)@@@list("amy_chou" "2015/01/12 09:57:30" nil "P143000034-PC" "5s-ippbt-sk.x01")@@@list("jennifer_hsu" "2015/01/12 14:36:41" nil "p143000039-pc" "5s-ippbt-sk.x01") | list("[Spacing] VCC" "9.Shape to Route Keepout" "0 MIL [DEFAULT]" "0 MIL" "0.00 MIL" "DRC ERROR CLASS/VCC" "[Shape] Route Keepout/All ((3031.18 -37.68) (3094.81 25.94))" "[Vcc Shape] GND ((-373.71 -332.37) (4468.18 4481.96))" list(3094.810000 -5.870000) nil)@@@list("amy_chou" "2015/01/12 09:57:27" nil "P143000034-PC" "5s-ippbt-sk.x01")@@@list("jennifer_hsu" "2015/01/12 14:36:38" nil "p143000039-pc" "5s-ippbt-sk.x01") | list("[Spacing] VCC" "1.Shape to Route Keepout" "0 MIL [DEFAULT]" "0 MIL" "0.00 MIL" "DRC ERROR CLASS/VCC" "[Shape] Route Keepout/All ((3082.5 3563.84) (3161.12 3642.46))" "[Vcc Shape] GND ((-373.71 -332.37) (4468.18 4481.96))" list(3121.810000 3642.460000) nil)@@@list("amy_chou" "2015/01/12 17:57:26" nil "P143000034-PC" "5s-ippbt-sk.x01")@@@list("jennifer_hsu" "2015/01/12 18:35:51" nil "p143000039-pc" "5s-ippbt-sk.x01") | list("[Spacing] VCC" "8.Shape to Route Keepout" "0 MIL [DEFAULT]" "0 MIL" "0.00 MIL" "DRC ERROR CLASS/VCC" "[Shape] Route Keepout/All ((3540.94 -76.81) (3604.57 -13.19))" "[Vcc Shape] GND ((-373.71 -332.37) (4468.18 4481.96))" list(3604.570000 -45.000000) nil)@@@list("amy_chou" "2015/01/12 09:57:26" nil "P143000034-PC" "5s-ippbt-sk.x01")@@@list("jennifer_hsu" "2015/01/12 14:36:38" nil "p143000039-pc" "5s-ippbt-sk.x01") | list("[Spacing] VCC" "10.Shape to Route Keepout" "0 MIL [DEFAULT]" "0 MIL" "0.00 MIL" "DRC ERROR CLASS/VCC" "[Shape] Route Keepout/All ((4155.45 329.33) (4242.07 415.95))" "[Vcc Shape] GND ((-373.71 -332.37) (4468.18 4481.96))" list(4242.070000 372.640000) nil)@@@list("amy_chou" "2015/01/12 09:57:27" nil "P143000034-PC" "5s-ippbt-sk.x01")@@@list("jennifer_hsu" "2015/01/12 14:36:38" nil "p143000039-pc" "5s-ippbt-sk.x01") | list("[Spacing] VCC" "17.Shape to Route Keepin" "0 MIL [DEFAULT]" "0 MIL" "0.00 MIL" "DRC ERROR CLASS/VCC" "[Shape] Route Keepin/All ((-373.71 -332.37) (4468.18 4481.96))" "[Vcc Shape] GND ((-373.71 -332.37) (4468.18 4481.96))" list(4299.650000 2680.720000) nil)@@@list("amy_chou" "2015/01/12 09:57:31" nil "P143000034-PC" "5s-ippbt-sk.x01")@@@list("jennifer_hsu" "2015/01/12 14:36:41" nil "p143000039-pc" "5s-ippbt-sk.x01") | list("[Spacing] VCC" "12.Shape to Route Keepout" "0 MIL [DEFAULT]" "0 MIL" "0.00 MIL" "DRC ERROR CLASS/VCC" "[Shape] Route Keepout/All ((4283.59 1394.18) (4509.57 1954.0))" "[Vcc Shape] GND ((-373.71 -332.37) (4468.18 4481.96))" list(4339.850000 1855.520000) nil)@@@list("amy_chou" "2015/01/12 09:57:28" nil "P143000034-PC" "5s-ippbt-sk.x01")@@@list("jennifer_hsu" "2015/01/12 14:36:39" nil "p143000039-pc" "5s-ippbt-sk.x01") | list("[Spacing] VCC" "13.Shape to Route Keepout" "0 MIL [DEFAULT]" "0 MIL" "0.00 MIL" "DRC ERROR CLASS/VCC" "[Shape] Route Keepout/All ((4243.45 2217.33) (4476.12 2781.09))" "[Vcc Shape] GND ((-373.71 -332.37) (4468.18 4481.96))" list(4468.180000 2780.380000) nil)@@@list("amy_chou" "2015/01/12 09:57:28" nil "P143000034-PC" "5s-ippbt-sk.x01")@@@list("jennifer_hsu" "2015/01/12 14:36:39" nil "p143000039-pc" "5s-ippbt-sk.x01")
IN1: list("[Spacing] IN1" "19.Drill Hole to Pin" "8 MIL [DEFAULT]" "7.39 MIL" "0.61 MIL" "DRC ERROR CLASS/IN1" "[ThruPin] Dummy (<uTiL>cId2813<uTiL>.3) (3063.0 -5.87)" "[ThruPin] Q32_C (<uTiL>cId2813<uTiL>.L2) (3110.24 2.0)" list(3082.730000 -2.580000) nil)@@@list("amy_chou" "2015/01/12 09:57:31" nil "P143000034-PC" "5s-ippbt-sk.x01")@@@list("jennifer_hsu" "2015/01/12 14:36:42" nil "p143000039-pc" "5s-ippbt-sk.x01") | list("[Spacing] IN1" "18.Drill Hole to Pin" "8 MIL [DEFAULT]" "7.39 MIL" "0.61 MIL" "DRC ERROR CLASS/IN1" "[ThruPin] Dummy (<uTiL>cId2813<uTiL>.4) (3157.48 -5.87)" "[ThruPin] Q32_C (<uTiL>cId2813<uTiL>.L2) (3110.24 2.0)" list(3137.750000 -2.580000) nil)@@@list("amy_chou" "2015/01/12 09:57:32" nil "P143000034-PC" "5s-ippbt-sk.x01")@@@list("jennifer_hsu" "2015/01/12 14:36:41" nil "p143000039-pc" "5s-ippbt-sk.x01") | list("[Spacing] IN1" "20.Drill Hole to Pin" "8 MIL [DEFAULT]" "7.39 MIL" "0.61 MIL" "DRC ERROR CLASS/IN1" "[ThruPin] Dummy (<uTiL>cId4667<uTiL>.3) (3572.76 -45.0)" "[ThruPin] PWR_LED- (<uTiL>cId4667<uTiL>.L2) (3620.0 -37.13)" list(3592.490000 -41.710000) nil)@@@list("amy_chou" "2015/01/12 09:57:32" nil "P143000034-PC" "5s-ippbt-sk.x01")@@@list("jennifer_hsu" "2015/01/12 14:36:42" nil "p143000039-pc" "5s-ippbt-sk.x01") | list("[Spacing] IN1" "21.Drill Hole to Pin" "8 MIL [DEFAULT]" "7.39 MIL" "0.61 MIL" "DRC ERROR CLASS/IN1" "[ThruPin] Dummy (<uTiL>cId4667<uTiL>.4) (3667.24 -45.0)" "[ThruPin] PWR_LED- (<uTiL>cId4667<uTiL>.L2) (3620.0 -37.13)" list(3647.510000 -41.710000) nil)@@@list("amy_chou" "2015/01/12 09:57:33" nil "P143000034-PC" "5s-ippbt-sk.x01")@@@list("jennifer_hsu" "2015/01/12 14:36:42" nil "p143000039-pc" "5s-ippbt-sk.x01")
IN2: list("[Spacing] IN2" "23.Drill Hole to Pin" "8 MIL [DEFAULT]" "7.39 MIL" "0.61 MIL" "DRC ERROR CLASS/IN2" "[ThruPin] Dummy (<uTiL>cId2813<uTiL>.3) (3063.0 -5.87)" "[ThruPin] Q32_C (<uTiL>cId2813<uTiL>.L2) (3110.24 2.0)" list(3082.730000 -2.580000) nil)@@@list("amy_chou" "2015/01/12 09:57:33" nil "P143000034-PC" "5s-ippbt-sk.x01")@@@list("jennifer_hsu" "2015/01/12 14:36:43" nil "p143000039-pc" "5s-ippbt-sk.x01") | list("[Spacing] IN2" "22.Drill Hole to Pin" "8 MIL [DEFAULT]" "7.39 MIL" "0.61 MIL" "DRC ERROR CLASS/IN2" "[ThruPin] Dummy (<uTiL>cId2813<uTiL>.4) (3157.48 -5.87)" "[ThruPin] Q32_C (<uTiL>cId2813<uTiL>.L2) (3110.24 2.0)" list(3137.750000 -2.580000) nil)@@@list("amy_chou" "2015/01/12 09:57:34" nil "P143000034-PC" "5s-ippbt-sk.x01")@@@list("jennifer_hsu" "2015/01/12 14:36:43" nil "p143000039-pc" "5s-ippbt-sk.x01") | list("[Spacing] IN2" "24.Drill Hole to Pin" "8 MIL [DEFAULT]" "7.39 MIL" "0.61 MIL" "DRC ERROR CLASS/IN2" "[ThruPin] Dummy (<uTiL>cId4667<uTiL>.3) (3572.76 -45.0)" "[ThruPin] PWR_LED- (<uTiL>cId4667<uTiL>.L2) (3620.0 -37.13)" list(3592.490000 -41.710000) nil)@@@list("amy_chou" "2015/01/12 09:57:35" nil "P143000034-PC" "5s-ippbt-sk.x01")@@@list("jennifer_hsu" "2015/01/12 14:36:43" nil "p143000039-pc" "5s-ippbt-sk.x01") | list("[Spacing] IN2" "25.Drill Hole to Pin" "8 MIL [DEFAULT]" "7.39 MIL" "0.61 MIL" "DRC ERROR CLASS/IN2" "[ThruPin] Dummy (<uTiL>cId4667<uTiL>.4) (3667.24 -45.0)" "[ThruPin] PWR_LED- (<uTiL>cId4667<uTiL>.L2) (3620.0 -37.13)" list(3647.510000 -41.710000) nil)@@@list("amy_chou" "2015/01/12 09:57:35" nil "P143000034-PC" "5s-ippbt-sk.x01")@@@list("jennifer_hsu" "2015/01/12 14:36:44" nil "p143000039-pc" "5s-ippbt-sk.x01")
